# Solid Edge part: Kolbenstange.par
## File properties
Username: bmolnar
Dokumentum tartalom típus: 0
Author: bmolnar
Last saved by: bmolnar
Revision: 80
Sűrűség: 0,000 kg/m^3
Pontosság: 0,990
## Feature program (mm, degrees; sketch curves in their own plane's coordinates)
base feature "unnamed BaseFeature 1"
sketch for "unnamed Protrusion 1" plane through (18.4, 0, 0) normal (1, 0, 0) x-axis (0, 1, 0)
  circle centre (0, 0) radius 8
extrude "unnamed Protrusion 1" add finite 19.7 along +normal
sketch for "Kihúzás_2" #1 plane through (18.4, 0, 0) normal (1, 0, 0) x-axis (0, 1, 0)
  circle centre (0, 0) radius 4
sketch for "Kihúzás_2" #2 plane through (18.4, 0, 0) normal (1, 0, 0) x-axis (0, 1, 0)
  circle centre (0, 0) radius 8
extrude "Kihúzás_2" add finite 5.5 along -normal
sketch for "Furat_1" plane through (-13, 0, 0.0012) normal (-1, 0, 0) x-axis (0, 0, 1)
  hole centre (-0.0012, 0) bore radius 1.621
hole "Furat_1" nominal diameter 4 finite  VBottomAngle = 118 deg; ThreadDepth = 9 mm
chamfer "Letörés_1" setback 0.2  SetBackValue2 = 45 deg
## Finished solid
Body 1: solid body, 18 faces, 24 edges, 8 vertices.
  Faces by surface: plane 8, cylinder 5, cone 3, torus 2
  Edges by curve: circle 14, line 6, curve on surface 2, ellipse 2
Bounding box of the edges (mm; curved faces can reach further): 53.100 x 16.000 x 16.000, from (-15, -8, -8) to (38.1, 8, 8).
Cylindrical faces by radius (mm): R1.621 x2, R2.125 x1, R4 x1, R8 x1
Conical faces (half-angle, radius in mm at the cone's reference point): 45 deg R1.821 x1, 45 deg R2.225 x1, 59 deg R1.621 x1
Toroidal faces (ring radius, tube radius in mm): R1.925 r0.2 x1, R2.7 r1.3 x1
Planar faces by outward normal: +x 1, +z 1, -x 3, -z 1, oblique 2
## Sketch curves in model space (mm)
circle centre (18.4, 0, 0) radius 8
circle centre (18.4, 0, 0) radius 4
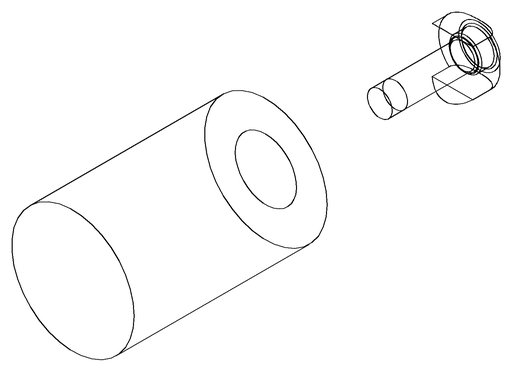
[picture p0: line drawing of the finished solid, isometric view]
